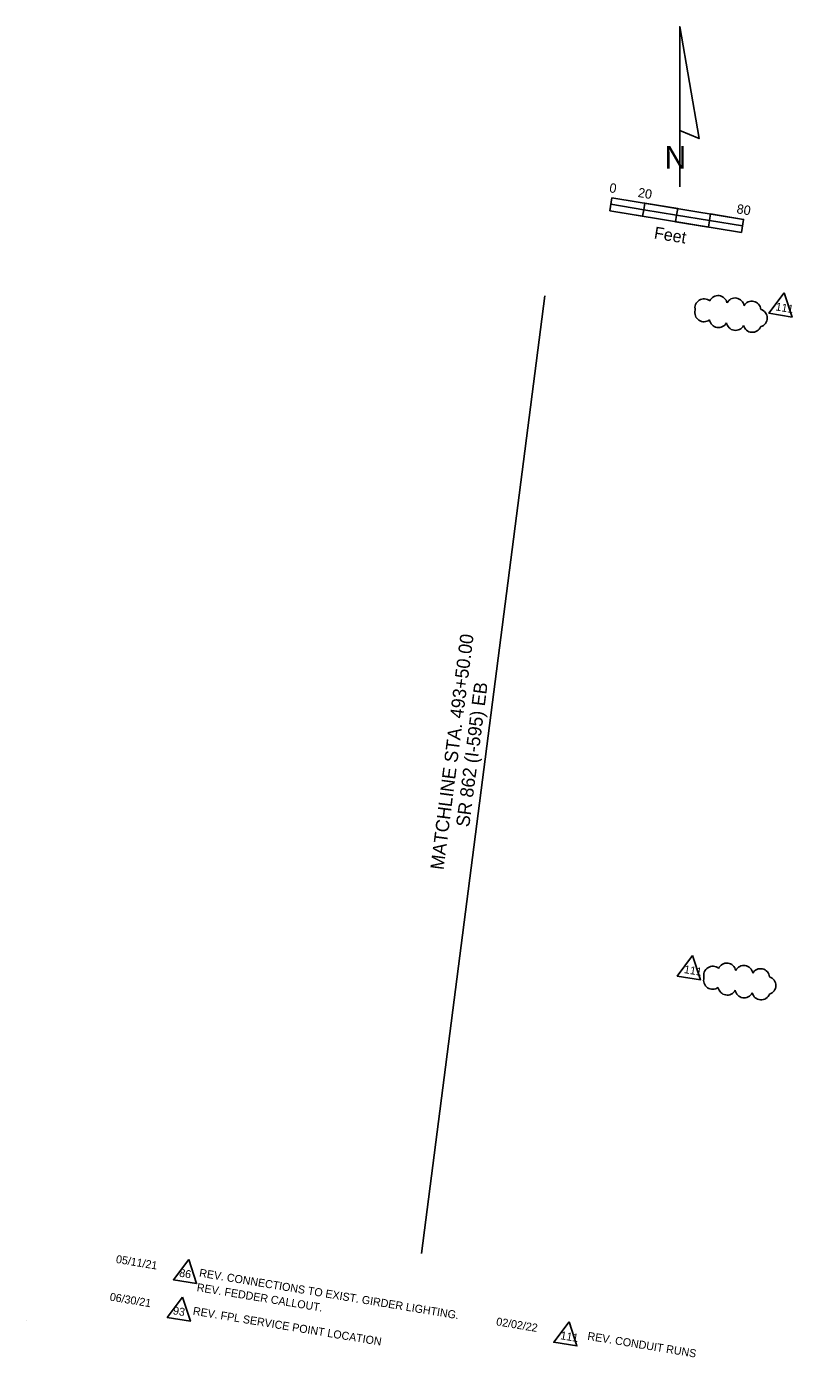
# Model space of a CAD drawing. Extents: x 927483 to 928746, y 636242 to 637203.
# Drawn here: x 927483 to 927943, y 636404 to 637203 of the extents above; entities that cross this region are included whole.
import ezdxf

# ---------------------------------------------------------------- set-up
doc = ezdxf.new("R2010")
doc.units = 0
for name, color, linetype in [('AdhocPoint_dp', 7, 'Continuous'), ('Cloud_dp', 7, 'Continuous'), ('MatchLines_dp', 7, 'Continuous'), ('NorthArw_dp', 7, 'Continuous'), ('Scale_dp', 7, 'Continuous')]:
    doc.layers.add(name, color=color, linetype=linetype)

msp = doc.modelspace()

# ---------------------------------------------------------------- linework, layer by layer
at = {"layer": 'AdhocPoint_dp'}
msp.add_line((927483.47, 636426.68), (927483.47, 636426.68), dxfattribs=at)
at = {"layer": 'Cloud_dp'}
for points in [[(927937.65, 637042.9), (927928.5, 637030.67), (927942.39, 637028.37)], [(927882.74, 636645.45), (927873.59, 636633.22), (927887.49, 636630.92)], [(927580.68, 636463.27), (927571.53, 636451.03), (927585.42, 636448.74)], [(927576.96, 636440.67), (927567.8, 636428.43), (927581.7, 636426.14)], [(927808.67, 636425.85), (927799.52, 636413.61), (927813.41, 636411.32)]]:
    msp.add_lwpolyline(points, close=True, dxfattribs=at)
for centre, start, end in [((927889.62, 637033.96), 49.77309, 194.77309), ((927898.07, 637035.88), 10.81232, 155.81232), ((927908.24, 637034.45), 8.20535, 153.20535), ((927918.31, 637032.54), 5.2898, 150.2898), ((927889.56, 637031.01), 163.13084, 308.13084), ((927922.05, 637027.88), 287.14219, 72.14219), ((927898.28, 637027.51), 188.13813, 333.13813), ((927908.49, 637025.84), 188.21634, 333.21634), ((927918.6, 637024.68), 193.70912, 338.70912), ((927894.84, 636633.63), 49.77309, 194.77309), ((927903.29, 636635.55), 10.81232, 155.81232), ((927913.45, 636634.12), 8.20535, 153.20535), ((927894.78, 636630.67), 163.13084, 308.13084), ((927923.53, 636632.2), 5.2898, 150.2898), ((927927.27, 636627.55), 287.14219, 72.14219), ((927903.5, 636627.18), 188.13813, 333.13813), ((927913.71, 636625.5), 188.21634, 333.21634), ((927923.82, 636624.34), 193.70912, 338.70912)]:
    msp.add_arc(centre, 5.42, start, end, dxfattribs=at)
at = {"layer": 'MatchLines_dp'}
msp.add_line((927794.09, 637041.24), (927720.24, 636466.75), dxfattribs=at)
at = {"layer": 'NorthArw_dp'}
msp.add_line((927875.11, 637106.63), (927875.11, 637202.63), dxfattribs=at)
msp.add_lwpolyline([(927875.11, 637140.23), (927875.11, 637202.63), (927886.63, 637135.43)], close=True, dxfattribs=at)
at = {"layer": 'Scale_dp'}
for p, q in [((927834.37, 637100.01), (927833.07, 637092.11)), ((927913.31, 637086.99), (927834.37, 637100.01)), ((927833.07, 637092.11), (927912, 637079.1)), ((927912, 637079.1), (927913.31, 637086.99))]:
    msp.add_line(p, q, dxfattribs=at)
for points in [[(927833.07, 637092.11), (927833.72, 637096.06), (927853.45, 637092.81), (927852.8, 637088.86)], [(927853.45, 637092.81), (927854.11, 637096.75), (927873.84, 637093.5), (927873.19, 637089.55)], [(927872.54, 637085.61), (927873.19, 637089.55), (927892.92, 637086.3), (927892.27, 637082.35)], [(927892.92, 637086.3), (927893.57, 637090.25), (927913.31, 637086.99), (927912.66, 637083.05)]]:
    msp.add_lwpolyline(points, close=True, dxfattribs=at)

# ---------------------------------------------------------------- texts
at = {"layer": 'Cloud_dp'}
for s, p in [('111', (927932.25, 637032.49)), ('111', (927877.35, 636635.04)), ('05/11/21', (927536.77, 636461.2)), ('86', (927574.66, 636452.96)), ('REV. CONNECTIONS TO EXIST. GIRDER LIGHTING. ', (927586.68, 636452.97)), ('REV. FEDDER CALLOUT.', (927585.24, 636444.29)), ('06/30/21', (927533.05, 636438.6)), ('93', (927570.93, 636430.36)), ('REV. FPL SERVICE POINT LOCATION', (927582.91, 636430.14)), ('02/02/22', (927764.76, 636423.78)), ('111', (927803.27, 636415.44)), ('REV. CONDUIT RUNS', (927819.47, 636415.08))]:
    msp.add_text(s, height=4.8, rotation=350.63813, dxfattribs=at).set_placement(p)
at = {"layer": 'MatchLines_dp'}
for s, p in [('MATCHLINE STA. 493+50.00', (927733.41, 636696.57)), ('SR 862 (I-595) EB', (927748.81, 636722.24))]:
    msp.add_text(s, height=8, rotation=82.67462, dxfattribs=at).set_placement(p)
at = {"layer": 'NorthArw_dp'}
msp.add_text('N', height=13.43, dxfattribs=at).set_placement((927865.99, 637117.5))
at = {"layer": 'Scale_dp'}
for s, height, p in [('0', 5.6, (927832.56, 637103.35)), ('20', 5.6, (927849.7, 637100.52)), ('80', 5.6, (927908.88, 637090.76)), ('Feet', 7.2, (927859.28, 637075.63))]:
    msp.add_text(s, height=height, rotation=350.63813, dxfattribs=at).set_placement(p)

doc.saveas('drawing.dxf')
